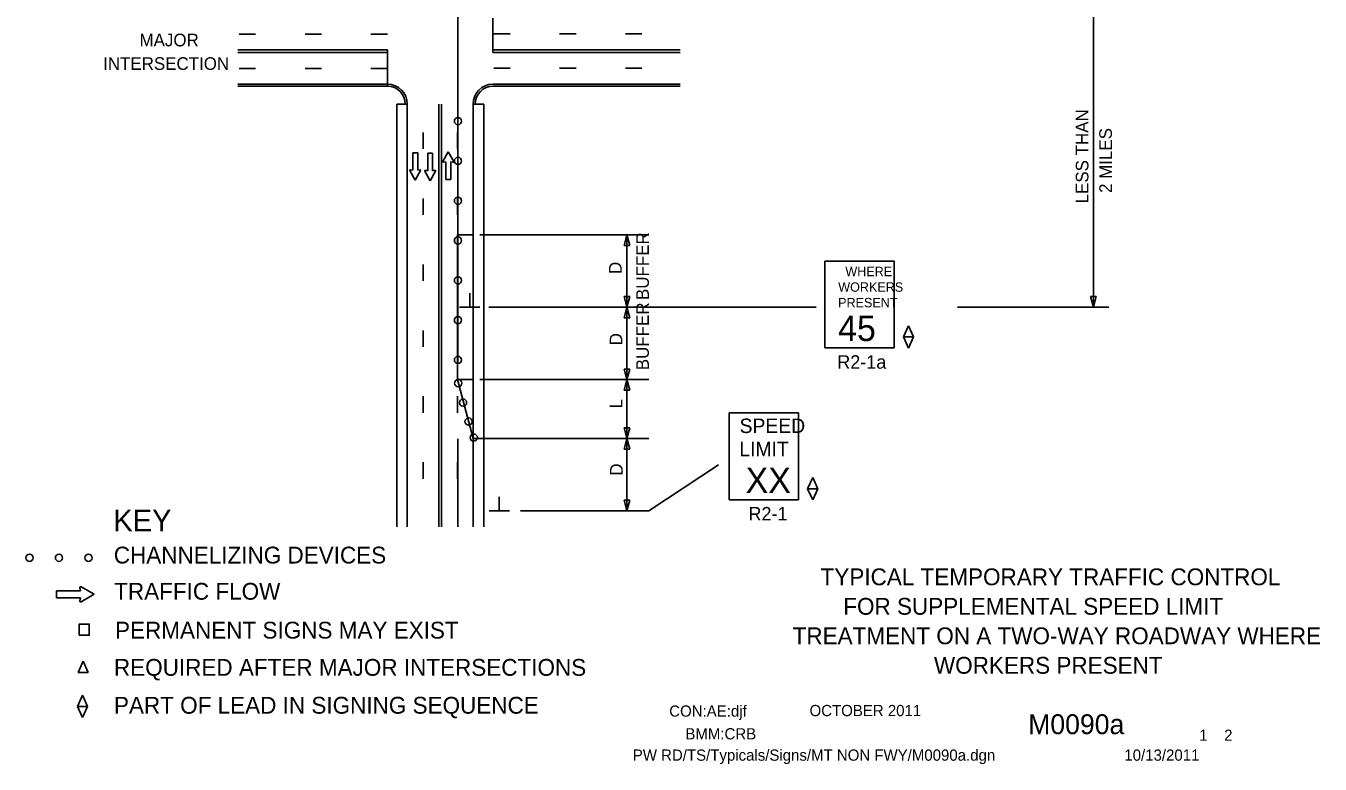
# Model space of a CAD drawing. Extents: x 16735 to 18480, y 5932 to 6927.
# Drawn here: x 16735 to 17451, y 5932 to 6340 of the extents above; entities that cross this region are included whole.
import ezdxf

# ---------------------------------------------------------------- set-up
doc = ezdxf.new("R2010")
doc.units = 0
for name, color, linetype in [('ALI_LEGAL_EX', 7, 'Continuous'), ('BORDER_SIGNAL_WO', 7, 'Continuous'), ('Level 44', 7, 'Continuous'), ('MT_SCRATCH_LEVEL_E', 7, 'Continuous'), ('PAVT_EDGE_EX', 7, 'Continuous'), ('TRAFFIC_SIGNS_PR', 7, 'Continuous'), ('TYPICAL_TEXT_DIMEN_EX', 7, 'Continuous'), ('TYPICAL_TEXT_DIMEN_PR', 7, 'Continuous')]:
    doc.layers.add(name, color=color, linetype=linetype)

msp = doc.modelspace()

# ---------------------------------------------------------------- linework, layer by layer
at = {"layer": 'ALI_LEGAL_EX'}
for points in [[(16852.86, 6335.27), (16861.98, 6335.27)], [(16889.31, 6335.27), (16898.43, 6335.27)], [(16925.76, 6335.27), (16934.88, 6335.27)], [(16993.62, 6335.41), (17002.73, 6335.41)], [(17030.07, 6335.41), (17039.18, 6335.41)], [(17066.52, 6335.41), (17075.63, 6335.41)], [(16852.86, 6316.31), (16861.98, 6316.31)], [(16889.31, 6316.31), (16898.43, 6316.31)], [(16925.76, 6316.31), (16934.88, 6316.31)], [(16993.62, 6316.45), (17002.73, 6316.45)], [(17030.07, 6316.45), (17039.18, 6316.45)], [(17066.52, 6316.45), (17075.63, 6316.45)], [(16954.56, 6271.78), (16954.56, 6280.89)], [(16973.51, 6271.78), (16973.51, 6280.89)], [(16954.56, 6235.33), (16954.56, 6244.44)], [(16973.51, 6235.33), (16973.51, 6244.44)], [(16954.56, 6198.88), (16954.56, 6207.99)], [(16973.51, 6198.88), (16973.51, 6207.99)], [(16954.56, 6162.43), (16954.56, 6171.54)], [(16973.51, 6162.43), (16973.51, 6171.54)], [(16954.56, 6125.98), (16954.56, 6135.09)], [(16973.51, 6125.98), (16973.51, 6135.09)], [(16954.56, 6089.53), (16954.56, 6098.64)], [(16973.51, 6089.53), (16973.51, 6098.64)]]:
    msp.add_lwpolyline(points, dxfattribs=at)
at = {"layer": 'MT_SCRATCH_LEVEL_E'}
for p, q in [((16965.49, 6264.93), (16968.51, 6270.21)), ((16965.49, 6264.93), (16968.51, 6270.21)), ((16968.51, 6270.21), (16971.5, 6264.93)), ((16968.51, 6270.21), (16971.5, 6264.93)), ((16948.86, 6260.07), (16948.86, 6269.73)), ((16948.86, 6269.73), (16951.59, 6269.73)), ((16948.86, 6260.07), (16948.86, 6269.73)), ((16948.86, 6269.73), (16951.59, 6269.73)), ((16951.59, 6269.73), (16951.59, 6260.07)), ((16951.59, 6269.73), (16951.59, 6260.07)), ((16957.12, 6259.77), (16957.12, 6269.44)), ((16957.12, 6269.44), (16959.85, 6269.44)), ((16957.12, 6259.77), (16957.12, 6269.44)), ((16957.12, 6269.44), (16959.85, 6269.44)), ((16959.85, 6269.44), (16959.85, 6259.77)), ((16959.85, 6269.44), (16959.85, 6259.77)), ((16967.13, 6264.66), (16965.83, 6264.43)), ((16967.13, 6264.66), (16965.83, 6264.43)), ((16967.13, 6255), (16967.13, 6264.66)), ((16967.13, 6255), (16967.13, 6264.66)), ((16971.15, 6264.43), (16969.86, 6264.66)), ((16969.86, 6264.66), (16969.86, 6255)), ((16971.15, 6264.43), (16969.86, 6264.66)), ((16969.86, 6264.66), (16969.86, 6255)), ((16950.21, 6254.52), (16947.21, 6259.8)), ((16950.21, 6254.52), (16947.21, 6259.8)), ((16947.56, 6260.3), (16948.86, 6260.07)), ((16947.56, 6260.3), (16948.86, 6260.07)), ((16953.23, 6259.8), (16950.21, 6254.52)), ((16953.23, 6259.8), (16950.21, 6254.52)), ((16951.59, 6260.07), (16952.88, 6260.3)), ((16951.59, 6260.07), (16952.88, 6260.3)), ((16958.47, 6254.22), (16955.47, 6259.5)), ((16958.47, 6254.22), (16955.47, 6259.5)), ((16955.82, 6260), (16957.12, 6259.77)), ((16955.82, 6260), (16957.12, 6259.77)), ((16961.49, 6259.5), (16958.47, 6254.22)), ((16961.49, 6259.5), (16958.47, 6254.22)), ((16959.85, 6259.77), (16961.14, 6260)), ((16959.85, 6259.77), (16961.14, 6260)), ((16969.86, 6255), (16967.13, 6255)), ((16969.86, 6255), (16967.13, 6255)), ((16765.07, 6027.54), (16751.81, 6027.54)), ((16751.81, 6027.54), (16751.81, 6023.8)), ((16765.07, 6027.54), (16751.81, 6027.54)), ((16751.81, 6027.54), (16751.81, 6023.8)), ((16764.75, 6029.32), (16765.07, 6027.54)), ((16764.75, 6029.32), (16765.07, 6027.54)), ((16772.68, 6025.69), (16765.44, 6029.8)), ((16772.68, 6025.69), (16765.44, 6029.8)), ((16751.81, 6023.8), (16765.07, 6023.8)), ((16751.81, 6023.8), (16765.07, 6023.8)), ((16765.07, 6023.8), (16764.75, 6022.02)), ((16765.07, 6023.8), (16764.75, 6022.02)), ((16765.44, 6021.55), (16772.68, 6025.69)), ((16765.44, 6021.55), (16772.68, 6025.69))]:
    msp.add_line(p, q, dxfattribs=at)
for centre, radius, start, end in [((16965.78, 6264.77), 0.337, 150.22688, 279.96381), ((16965.78, 6264.77), 0.337, 150.22688, 279.96381), ((16971.21, 6264.77), 0.337, 260.03619, 29.57516), ((16971.21, 6264.77), 0.337, 260.03619, 29.57516), ((16947.51, 6259.96), 0.337, 80.03619, 209.57516), ((16947.51, 6259.96), 0.337, 80.03619, 209.57516), ((16952.93, 6259.96), 0.337, 330.22688, 99.96381), ((16952.93, 6259.96), 0.337, 330.22688, 99.96381), ((16955.77, 6259.67), 0.337, 80.03619, 209.57516), ((16955.77, 6259.67), 0.337, 80.03619, 209.57516), ((16961.19, 6259.67), 0.337, 330.22688, 99.96381), ((16961.19, 6259.67), 0.337, 330.22688, 99.96381), ((16765.21, 6029.4), 0.463, 60.42484, 189.96381), ((16765.21, 6029.4), 0.463, 60.42484, 189.96381), ((16765.21, 6021.95), 0.463, 170.03619, 299.77312), ((16765.21, 6021.95), 0.463, 170.03619, 299.77312)]:
    msp.add_arc(centre, radius, start, end, dxfattribs=at)
at = {"layer": 'PAVT_EDGE_EX'}
for p, q in [((16973.87, 6153.19), (16973.87, 6927.02)), ((16993.2, 6325.06), (16993.2, 6344.01)), ((16934.88, 6326.52), (16852.04, 6326.52)), ((16934.88, 6325.06), (16852.04, 6325.06)), ((16934.88, 6326.52), (16934.88, 6306.47)), ((17096.82, 6326.52), (16993.2, 6326.52)), ((17096.82, 6325.06), (16993.2, 6325.06)), ((16934.88, 6307.56), (16852.04, 6307.56)), ((16934.88, 6306.47), (16852.04, 6306.47)), ((17096.82, 6307.56), (16993.2, 6307.56)), ((17096.82, 6306.47), (16993.2, 6306.47)), ((16939.98, 6296.63), (16945.81, 6296.63)), ((16939.98, 6062.98), (16939.98, 6296.63)), ((16945.81, 6062.98), (16945.81, 6296.63)), ((16963.31, 6062.98), (16963.31, 6296.63)), ((16964.77, 6062.98), (16964.77, 6296.63)), ((16988.09, 6296.63), (16982.26, 6296.63)), ((16982.26, 6062.98), (16982.26, 6296.63)), ((16988.09, 6062.98), (16988.09, 6296.63)), ((16973.87, 6062.98), (16973.87, 6111.56))]:
    msp.add_line(p, q, dxfattribs=at)
msp.add_lwpolyline([(16982.26, 6224.31), (16973.51, 6224.31), (16973.51, 6144.31), (16982.26, 6144.31)], close=True, dxfattribs=at)
for centre in [(16973.87, 6287.19), (16973.87, 6265.19), (16973.87, 6243.19), (16973.87, 6221.19), (16973.87, 6199.19), (16973.87, 6177.19), (16973.87, 6155.19)]:
    msp.add_circle(centre, 2, dxfattribs=at)
for centre, radius, start, end in [((16934.88, 6296.63), 10.94, 0, 90), ((16934.88, 6296.63), 9.84, 0, 90), ((16993.2, 6296.63), 10.94, 90, 180), ((16993.2, 6296.63), 9.84, 90, 180)]:
    msp.add_arc(centre, radius, start, end, dxfattribs=at)
at = {"layer": 'TRAFFIC_SIGNS_PR'}
for p, q in [((17176.77, 6209.8), (17215.17, 6209.8)), ((17176.77, 6161.8), (17176.77, 6209.8)), ((17215.17, 6161.8), (17215.17, 6209.8)), ((17176.77, 6161.8), (17215.17, 6161.8)), ((17123.84, 6125.93), (17162.24, 6125.93)), ((17123.84, 6077.93), (17123.84, 6125.93)), ((17162.24, 6077.93), (17162.24, 6125.93)), ((17123.84, 6077.93), (17162.24, 6077.93))]:
    msp.add_line(p, q, dxfattribs=at)
for points in [[(17222.99, 6174.07), (17220.19, 6167.9)], [(17220.19, 6167.9), (17222.99, 6174.07)], [(17225.78, 6167.9), (17222.99, 6174.07)], [(17222.99, 6174.07), (17225.78, 6167.9)], [(17220.19, 6167.9), (17225.78, 6167.9)], [(17225.78, 6167.9), (17220.19, 6167.9)], [(17222.99, 6161.73), (17220.19, 6167.9)], [(17220.19, 6167.9), (17225.78, 6167.9)], [(17225.78, 6167.9), (17220.19, 6167.9)], [(17220.19, 6167.9), (17222.99, 6161.73)], [(17225.78, 6167.9), (17222.99, 6161.73)], [(17222.99, 6161.73), (17225.78, 6167.9)], [(17170.05, 6090.21), (17167.25, 6084.04)], [(17167.25, 6084.04), (17170.05, 6090.21)], [(17167.25, 6084.04), (17172.85, 6084.04)], [(17172.85, 6084.04), (17167.25, 6084.04)], [(17170.05, 6077.87), (17167.25, 6084.04)], [(17167.25, 6084.04), (17172.85, 6084.04)], [(17172.85, 6084.04), (17167.25, 6084.04)], [(17167.25, 6084.04), (17170.05, 6077.87)], [(17172.85, 6084.04), (17170.05, 6090.21)], [(17170.05, 6090.21), (17172.85, 6084.04)], [(17172.85, 6084.04), (17170.05, 6077.87)], [(17170.05, 6077.87), (17172.85, 6084.04)], [(16766.58, 5988.65), (16763.78, 5982.48)], [(16763.78, 5982.48), (16766.58, 5988.65)], [(16769.37, 5982.48), (16766.58, 5988.65)], [(16766.58, 5988.65), (16769.37, 5982.48)], [(16763.78, 5982.48), (16769.37, 5982.48)], [(16769.37, 5982.48), (16763.78, 5982.48)], [(16766.17, 5969.85), (16763.37, 5963.68)], [(16763.37, 5963.68), (16766.17, 5969.85)], [(16768.96, 5963.68), (16766.17, 5969.85)], [(16766.17, 5969.85), (16768.96, 5963.68)], [(16763.37, 5963.68), (16768.96, 5963.68)], [(16768.96, 5963.68), (16763.37, 5963.68)], [(16766.17, 5957.51), (16763.37, 5963.68)], [(16763.37, 5963.68), (16768.96, 5963.68)], [(16768.96, 5963.68), (16763.37, 5963.68)], [(16763.37, 5963.68), (16766.17, 5957.51)], [(16768.96, 5963.68), (16766.17, 5957.51)], [(16766.17, 5957.51), (16768.96, 5963.68)]]:
    msp.add_lwpolyline(points, dxfattribs=at)
msp.add_lwpolyline([(16764.39, 6003.04), (16769.98, 6003.04), (16769.98, 6009.22), (16764.39, 6009.22)], close=True, dxfattribs=at)
for centre in [(16736.91, 6045.87), (16753.21, 6045.87), (16769.51, 6045.87)]:
    msp.add_circle(centre, 2, dxfattribs=at)
at = {"layer": 'TYPICAL_TEXT_DIMEN_PR'}
for p, q in [((17325.26, 6354.95), (17325.26, 6184.31)), ((17079.34, 6224.31), (16986.03, 6224.31)), ((17065.72, 6218.45), (17067.29, 6224.31)), ((17067.29, 6224.31), (17068.86, 6218.45)), ((17067.29, 6224.31), (17067.29, 6184.31)), ((17067.29, 6218.45), (17065.72, 6218.45)), ((17068.86, 6218.45), (17067.29, 6218.45)), ((16980.33, 6184.32), (16980.33, 6192.1)), ((16985.96, 6184.32), (16974.71, 6184.32)), ((17171.9, 6184.31), (16990.85, 6184.31)), ((17067.29, 6184.31), (17065.72, 6190.17)), ((17065.72, 6190.17), (17067.29, 6190.17)), ((17065.72, 6178.45), (17067.29, 6184.31)), ((17067.29, 6190.17), (17068.86, 6190.17)), ((17068.86, 6190.17), (17067.29, 6184.31)), ((17067.29, 6184.31), (17068.86, 6178.45)), ((17067.29, 6184.31), (17067.29, 6144.31)), ((17067.29, 6184.31), (17067.29, 6184.31)), ((17333.74, 6184.31), (17250.08, 6184.31)), ((17325.26, 6184.31), (17323.69, 6190.17)), ((17323.69, 6190.17), (17325.26, 6190.17)), ((17325.26, 6190.17), (17326.83, 6190.17)), ((17326.83, 6190.17), (17325.26, 6184.31)), ((17325.26, 6184.31), (17325.26, 6184.31)), ((17067.29, 6178.45), (17065.72, 6178.45)), ((17068.86, 6178.45), (17067.29, 6178.45)), ((17067.29, 6144.31), (17065.72, 6150.17)), ((17065.72, 6150.17), (17067.29, 6150.17)), ((17067.29, 6150.17), (17068.86, 6150.17)), ((17068.86, 6150.17), (17067.29, 6144.31)), ((16982.26, 6111.77), (16973.51, 6144.31)), ((17079.34, 6144.31), (16986.03, 6144.31)), ((17065.72, 6138.45), (17067.29, 6144.31)), ((17067.29, 6144.31), (17067.29, 6111.77)), ((17067.29, 6144.31), (17068.86, 6138.45)), ((17067.29, 6144.31), (17067.29, 6144.31)), ((17067.29, 6138.45), (17065.72, 6138.45)), ((17068.86, 6138.45), (17067.29, 6138.45)), ((17067.29, 6111.77), (17065.72, 6117.63)), ((17065.72, 6117.63), (17067.29, 6117.63)), ((17067.29, 6117.63), (17068.86, 6117.63)), ((17068.86, 6117.63), (17067.29, 6111.77)), ((17079.34, 6111.77), (16982.26, 6111.77)), ((17065.72, 6105.91), (17067.29, 6111.77)), ((17067.29, 6105.91), (17065.72, 6105.91)), ((17067.29, 6111.77), (17068.86, 6105.91)), ((17067.29, 6111.77), (17067.29, 6071.77)), ((17068.86, 6105.91), (17067.29, 6105.91)), ((17079.34, 6071.77), (17117.99, 6097.21)), ((16996.68, 6071.78), (16996.68, 6079.56)), ((17067.29, 6071.77), (17065.72, 6077.63)), ((17065.72, 6077.63), (17067.29, 6077.63)), ((17067.29, 6077.63), (17068.86, 6077.63)), ((17068.86, 6077.63), (17067.29, 6071.77)), ((17002.3, 6071.78), (16991.05, 6071.78)), ((17079.34, 6071.77), (17008.47, 6071.77)), ((17067.29, 6071.77), (17067.29, 6071.77))]:
    msp.add_line(p, q, dxfattribs=at)
for centre in [(16974.03, 6142.38), (16976.66, 6131.62), (16979.74, 6121.14), (16982.57, 6112.26)]:
    msp.add_circle(centre, 2, dxfattribs=at)

# ---------------------------------------------------------------- texts
at = {"layer": 'BORDER_SIGNAL_WO'}
for s, height, p in [('CON:AE:djf', 6.2, (17090.69, 5958.06)), ('    OCTOBER 2011    ', 6.2, (17159.08, 5958.34)), ('    M0090a   ', 11, (17272.86, 5948.38)), ('BMM:CRB   ', 6.2, (17099.62, 5945.49)), (' 1    2 ', 6.2, (17381.45, 5944.7)), ('PW RD/TS/Typicals/Signs/MT NON FWY/M0090a.dgn    ', 6.2, (17070.55, 5933.71)), ('10/13/2011    ', 6.2, (17342.4, 5933.71))]:
    msp.add_text(s, height=height, dxfattribs=at).set_placement(p)
at = {"layer": 'Level 44'}
for s, p in [('TYPICAL TEMPORARY TRAFFIC CONTROL', (17174.4, 6030.68)), ('FOR SUPPLEMENTAL SPEED LIMIT ', (17186.94, 6014.38)), ('TREATMENT ON A TWO-WAY ROADWAY WHERE ', (17158.94, 5998.08)), ('WORKERS PRESENT', (17237.1, 5981.78))]:
    msp.add_text(s, height=9.3, dxfattribs=at).set_placement(p)
at = {"layer": 'TRAFFIC_SIGNS_PR'}
for s, height, p in [('WHERE', 5.2, (17188.09, 6201.48)), ('WORKERS', 5.2, (17184.16, 6192.88)), ('PRESENT', 5.2, (17184.09, 6184.28)), ('45', 14.031, (17184.08, 6165.65)), ('R2-1a', 7.44, (17183.63, 6150.36)), ('SPEED', 8, (17129.6, 6114.8)), ('LIMIT', 8, (17129.44, 6102)), ('XX', 14.031, (17132.95, 6081.69)), ('R2-1', 7.44, (17134.51, 6066.49))]:
    msp.add_text(s, height=height, dxfattribs=at).set_placement(p)
at = {"layer": 'TYPICAL_TEXT_DIMEN_EX'}
for s, height, p in [('KEY', 12, (16783.29, 6060.53)), ('CHANNELIZING DEVICES', 9.3, (16783.53, 6042.7)), ('TRAFFIC FLOW', 9.3, (16783.75, 6022.7)), ('PERMANENT SIGNS MAY EXIST', 9.3, (16784.21, 6001.21)), ('REQUIRED AFTER MAJOR INTERSECTIONS', 9.3, (16783.61, 5980.64)), ('PART OF LEAD IN SIGNING SEQUENCE', 9.3, (16783.61, 5959.7))]:
    msp.add_text(s, height=height, dxfattribs=at).set_placement(p)
at = {"layer": 'TYPICAL_TEXT_DIMEN_PR'}
for s, rotation, p in [('MAJOR', 360, (16797.76, 6328.49)), ('INTERSECTION', 360, (16777.63, 6315.49)), ('LESS THAN', 90, (17322.51, 6241.71)), ('2 MILES', 90, (17335.51, 6247.47)), ('BUFFER', 90, (17079.45, 6188.31)), ('D', 90, (17064.39, 6202.67)), ('BUFFER', 90, (17079.45, 6149.52)), ('D', 90, (17064.73, 6163.28)), ('L', 90, (17064.73, 6128.4)), ('D', 90, (17064.97, 6091.22))]:
    msp.add_text(s, height=7, rotation=rotation, dxfattribs=at).set_placement(p)

doc.saveas('drawing.dxf')
